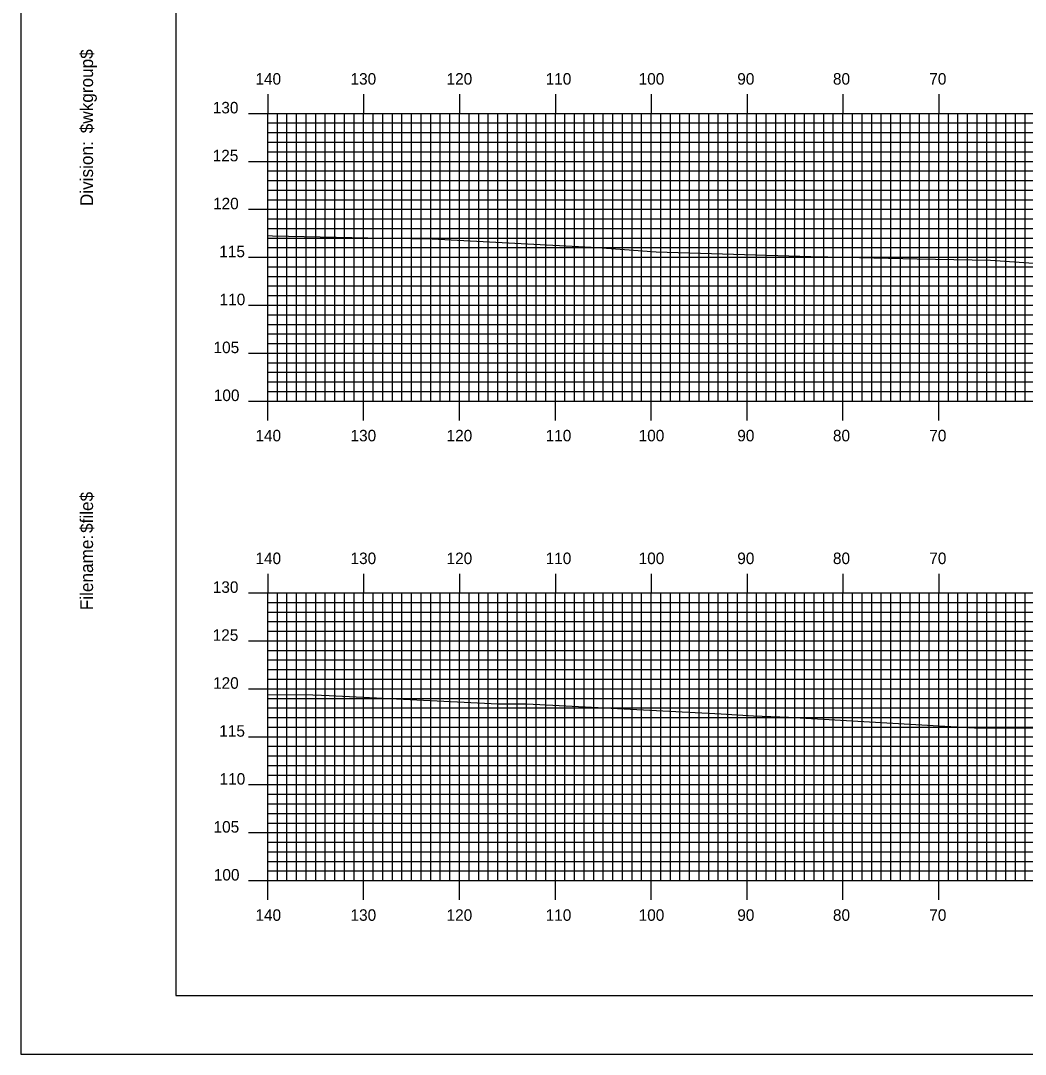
# Model space of a CAD drawing. Extents: x 1781073 to 1781416, y 442591 to 442811.
# Drawn here: x 1781073.1 to 1781177.9, y 442590.5 to 442698.3 of the extents above; entities that cross this region are included whole.
import ezdxf

# ---------------------------------------------------------------- set-up
doc = ezdxf.new("R2010")
doc.units = 0
for name, color, linetype in [('BORDER', 7, 'Continuous'), ('H_V ANNOTATION', 7, 'Continuous'), ('MAJOR', 7, 'Continuous'), ('MINOR', 7, 'Continuous'), ('PLOT BOUNDARY', 7, 'Continuous'), ('S_Roadway_Centerline', 7, 'Continuous')]:
    doc.layers.add(name, color=color, linetype=linetype)

msp = doc.modelspace()

# ---------------------------------------------------------------- linework, layer by layer
at = {"layer": 'BORDER'}
msp.add_lwpolyline([(1781089.29, 442596.67), (1781409.29, 442596.67), (1781409.29, 442806.67), (1781089.29, 442806.67)], close=True, dxfattribs=at)
at = {"layer": 'MAJOR'}
for p, q in [((1781098.89, 442690.67), (1781098.89, 442688.67)), ((1781108.89, 442690.67), (1781108.89, 442688.67)), ((1781118.89, 442690.67), (1781118.89, 442688.67)), ((1781128.89, 442690.67), (1781128.89, 442688.67)), ((1781138.89, 442690.67), (1781138.89, 442688.67)), ((1781148.89, 442690.67), (1781148.89, 442688.67)), ((1781158.89, 442690.67), (1781158.89, 442688.67)), ((1781168.89, 442690.67), (1781168.89, 442688.67)), ((1781096.89, 442688.67), (1781098.89, 442688.67)), ((1781098.89, 442688.67), (1781378.89, 442688.67)), ((1781098.89, 442658.67), (1781098.89, 442688.67)), ((1781098.89, 442658.67), (1781098.89, 442688.67)), ((1781098.89, 442688.67), (1781378.89, 442688.67)), ((1781108.89, 442658.67), (1781108.89, 442688.67)), ((1781118.89, 442658.67), (1781118.89, 442688.67)), ((1781128.89, 442658.67), (1781128.89, 442688.67)), ((1781138.89, 442658.67), (1781138.89, 442688.67)), ((1781148.89, 442658.67), (1781148.89, 442688.67)), ((1781158.89, 442658.67), (1781158.89, 442688.67)), ((1781168.89, 442658.67), (1781168.89, 442688.67)), ((1781096.89, 442683.67), (1781098.89, 442683.67)), ((1781098.89, 442683.67), (1781378.89, 442683.67)), ((1781096.89, 442678.67), (1781098.89, 442678.67)), ((1781098.89, 442678.67), (1781378.89, 442678.67)), ((1781096.89, 442673.67), (1781098.89, 442673.67)), ((1781098.89, 442673.67), (1781378.89, 442673.67)), ((1781096.89, 442668.67), (1781098.89, 442668.67)), ((1781098.89, 442668.67), (1781378.89, 442668.67)), ((1781096.89, 442663.67), (1781098.89, 442663.67)), ((1781098.89, 442663.67), (1781378.89, 442663.67)), ((1781096.89, 442658.67), (1781098.89, 442658.67)), ((1781098.89, 442658.67), (1781378.89, 442658.67)), ((1781098.89, 442658.67), (1781378.89, 442658.67)), ((1781098.89, 442656.66), (1781098.89, 442658.67)), ((1781108.89, 442656.66), (1781108.89, 442658.67)), ((1781118.89, 442656.66), (1781118.89, 442658.67)), ((1781128.89, 442656.66), (1781128.89, 442658.67)), ((1781138.89, 442656.66), (1781138.89, 442658.67)), ((1781148.89, 442656.66), (1781148.89, 442658.67)), ((1781158.89, 442656.66), (1781158.89, 442658.67)), ((1781168.89, 442656.66), (1781168.89, 442658.67)), ((1781098.89, 442640.67), (1781098.89, 442638.67)), ((1781108.89, 442640.67), (1781108.89, 442638.67)), ((1781118.89, 442640.67), (1781118.89, 442638.67)), ((1781128.89, 442640.67), (1781128.89, 442638.67)), ((1781138.89, 442640.67), (1781138.89, 442638.67)), ((1781148.89, 442640.67), (1781148.89, 442638.67)), ((1781158.89, 442640.67), (1781158.89, 442638.67)), ((1781168.89, 442640.67), (1781168.89, 442638.67)), ((1781096.89, 442638.67), (1781098.89, 442638.67)), ((1781098.89, 442638.67), (1781378.89, 442638.67)), ((1781098.89, 442608.67), (1781098.89, 442638.67)), ((1781098.89, 442608.67), (1781098.89, 442638.67)), ((1781098.89, 442638.67), (1781378.89, 442638.67)), ((1781108.89, 442608.67), (1781108.89, 442638.67)), ((1781118.89, 442608.67), (1781118.89, 442638.67)), ((1781128.89, 442608.67), (1781128.89, 442638.67)), ((1781138.89, 442608.67), (1781138.89, 442638.67)), ((1781148.89, 442608.67), (1781148.89, 442638.67)), ((1781158.89, 442608.67), (1781158.89, 442638.67)), ((1781168.89, 442608.67), (1781168.89, 442638.67)), ((1781096.89, 442633.67), (1781098.89, 442633.67)), ((1781098.89, 442633.67), (1781378.89, 442633.67)), ((1781096.89, 442628.67), (1781098.89, 442628.67)), ((1781098.89, 442628.67), (1781378.89, 442628.67)), ((1781096.89, 442623.67), (1781098.89, 442623.67)), ((1781098.89, 442623.67), (1781378.89, 442623.67)), ((1781096.89, 442618.67), (1781098.89, 442618.67)), ((1781098.89, 442618.67), (1781378.89, 442618.67)), ((1781096.89, 442613.67), (1781098.89, 442613.67)), ((1781098.89, 442613.67), (1781378.89, 442613.67)), ((1781096.89, 442608.67), (1781098.89, 442608.67)), ((1781098.89, 442608.67), (1781378.89, 442608.67)), ((1781098.89, 442608.67), (1781378.89, 442608.67)), ((1781098.89, 442606.66), (1781098.89, 442608.67)), ((1781108.89, 442606.66), (1781108.89, 442608.67)), ((1781118.89, 442606.66), (1781118.89, 442608.67)), ((1781128.89, 442606.66), (1781128.89, 442608.67)), ((1781138.89, 442606.66), (1781138.89, 442608.67)), ((1781148.89, 442606.66), (1781148.89, 442608.67)), ((1781158.89, 442606.66), (1781158.89, 442608.67)), ((1781168.89, 442606.66), (1781168.89, 442608.67))]:
    msp.add_line(p, q, dxfattribs=at)
at = {"layer": 'MINOR'}
for p, q in [((1781099.89, 442658.67), (1781099.89, 442688.67)), ((1781100.89, 442658.67), (1781100.89, 442688.67)), ((1781101.89, 442658.67), (1781101.89, 442688.67)), ((1781102.89, 442658.67), (1781102.89, 442688.67)), ((1781103.89, 442658.67), (1781103.89, 442688.67)), ((1781104.89, 442658.67), (1781104.89, 442688.67)), ((1781105.89, 442658.67), (1781105.89, 442688.67)), ((1781106.89, 442658.67), (1781106.89, 442688.67)), ((1781107.89, 442658.67), (1781107.89, 442688.67)), ((1781109.89, 442658.67), (1781109.89, 442688.67)), ((1781110.89, 442658.67), (1781110.89, 442688.67)), ((1781111.89, 442658.67), (1781111.89, 442688.67)), ((1781112.89, 442658.67), (1781112.89, 442688.67)), ((1781113.89, 442658.67), (1781113.89, 442688.67)), ((1781114.89, 442658.67), (1781114.89, 442688.67)), ((1781115.89, 442658.67), (1781115.89, 442688.67)), ((1781116.89, 442658.67), (1781116.89, 442688.67)), ((1781117.89, 442658.67), (1781117.89, 442688.67)), ((1781119.89, 442658.67), (1781119.89, 442688.67)), ((1781120.89, 442658.67), (1781120.89, 442688.67)), ((1781121.89, 442658.67), (1781121.89, 442688.67)), ((1781122.89, 442658.67), (1781122.89, 442688.67)), ((1781123.89, 442658.67), (1781123.89, 442688.67)), ((1781124.89, 442658.67), (1781124.89, 442688.67)), ((1781125.89, 442658.67), (1781125.89, 442688.67)), ((1781126.89, 442658.67), (1781126.89, 442688.67)), ((1781127.89, 442658.67), (1781127.89, 442688.67)), ((1781129.89, 442658.67), (1781129.89, 442688.67)), ((1781130.89, 442658.67), (1781130.89, 442688.67)), ((1781131.89, 442658.67), (1781131.89, 442688.67)), ((1781132.89, 442658.67), (1781132.89, 442688.67)), ((1781133.89, 442658.67), (1781133.89, 442688.67)), ((1781134.89, 442658.67), (1781134.89, 442688.67)), ((1781135.89, 442658.67), (1781135.89, 442688.67)), ((1781136.89, 442658.67), (1781136.89, 442688.67)), ((1781137.89, 442658.67), (1781137.89, 442688.67)), ((1781139.89, 442658.67), (1781139.89, 442688.67)), ((1781140.89, 442658.67), (1781140.89, 442688.67)), ((1781141.89, 442658.67), (1781141.89, 442688.67)), ((1781142.89, 442658.67), (1781142.89, 442688.67)), ((1781143.89, 442658.67), (1781143.89, 442688.67)), ((1781144.89, 442658.67), (1781144.89, 442688.67)), ((1781145.89, 442658.67), (1781145.89, 442688.67)), ((1781146.89, 442658.67), (1781146.89, 442688.67)), ((1781147.89, 442658.67), (1781147.89, 442688.67)), ((1781149.89, 442658.67), (1781149.89, 442688.67)), ((1781150.89, 442658.67), (1781150.89, 442688.67)), ((1781151.89, 442658.67), (1781151.89, 442688.67)), ((1781152.89, 442658.67), (1781152.89, 442688.67)), ((1781153.89, 442658.67), (1781153.89, 442688.67)), ((1781154.89, 442658.67), (1781154.89, 442688.67)), ((1781155.89, 442658.67), (1781155.89, 442688.67)), ((1781156.89, 442658.67), (1781156.89, 442688.67)), ((1781157.89, 442658.67), (1781157.89, 442688.67)), ((1781159.89, 442658.67), (1781159.89, 442688.67)), ((1781160.89, 442658.67), (1781160.89, 442688.67)), ((1781161.89, 442658.67), (1781161.89, 442688.67)), ((1781162.89, 442658.67), (1781162.89, 442688.67)), ((1781163.89, 442658.67), (1781163.89, 442688.67)), ((1781164.89, 442658.67), (1781164.89, 442688.67)), ((1781165.89, 442658.67), (1781165.89, 442688.67)), ((1781166.89, 442658.67), (1781166.89, 442688.67)), ((1781167.89, 442658.67), (1781167.89, 442688.67)), ((1781169.89, 442658.67), (1781169.89, 442688.67)), ((1781170.89, 442658.67), (1781170.89, 442688.67)), ((1781171.89, 442658.67), (1781171.89, 442688.67)), ((1781172.89, 442658.67), (1781172.89, 442688.67)), ((1781173.89, 442658.67), (1781173.89, 442688.67)), ((1781174.89, 442658.67), (1781174.89, 442688.67)), ((1781175.89, 442658.67), (1781175.89, 442688.67)), ((1781176.89, 442658.67), (1781176.89, 442688.67)), ((1781177.89, 442658.67), (1781177.89, 442688.67)), ((1781098.89, 442687.67), (1781378.89, 442687.67)), ((1781098.89, 442687.67), (1781100.9, 442687.67)), ((1781098.89, 442686.67), (1781378.89, 442686.67)), ((1781098.89, 442686.67), (1781100.9, 442686.67)), ((1781098.89, 442685.67), (1781378.89, 442685.67)), ((1781098.89, 442685.67), (1781100.9, 442685.67)), ((1781098.89, 442684.67), (1781378.89, 442684.67)), ((1781098.89, 442684.67), (1781100.9, 442684.67)), ((1781098.89, 442682.67), (1781378.89, 442682.67)), ((1781098.89, 442682.67), (1781100.9, 442682.67)), ((1781098.89, 442681.67), (1781378.89, 442681.67)), ((1781098.89, 442681.67), (1781100.9, 442681.67)), ((1781098.89, 442680.67), (1781378.89, 442680.67)), ((1781098.89, 442680.67), (1781100.9, 442680.67)), ((1781098.89, 442679.67), (1781378.89, 442679.67)), ((1781098.89, 442679.67), (1781100.9, 442679.67)), ((1781098.89, 442677.67), (1781378.89, 442677.67)), ((1781098.89, 442677.67), (1781100.9, 442677.67)), ((1781098.89, 442676.67), (1781378.89, 442676.67)), ((1781098.89, 442676.67), (1781100.9, 442676.67)), ((1781098.89, 442675.67), (1781378.89, 442675.67)), ((1781098.89, 442675.67), (1781100.9, 442675.67)), ((1781098.89, 442674.67), (1781378.89, 442674.67)), ((1781098.89, 442674.67), (1781100.9, 442674.67)), ((1781098.89, 442672.67), (1781378.89, 442672.67)), ((1781098.89, 442672.67), (1781100.9, 442672.67)), ((1781098.89, 442671.67), (1781378.89, 442671.67)), ((1781098.89, 442671.67), (1781100.9, 442671.67)), ((1781098.89, 442670.67), (1781378.89, 442670.67)), ((1781098.89, 442670.67), (1781100.9, 442670.67)), ((1781098.89, 442669.67), (1781378.89, 442669.67)), ((1781098.89, 442669.67), (1781100.9, 442669.67)), ((1781098.89, 442667.67), (1781378.89, 442667.67)), ((1781098.89, 442667.67), (1781100.9, 442667.67)), ((1781098.89, 442666.67), (1781378.89, 442666.67)), ((1781098.89, 442666.67), (1781100.9, 442666.67)), ((1781098.89, 442665.67), (1781378.89, 442665.67)), ((1781098.89, 442665.67), (1781100.9, 442665.67)), ((1781098.89, 442664.67), (1781378.89, 442664.67)), ((1781098.89, 442664.67), (1781100.9, 442664.67)), ((1781098.89, 442662.67), (1781378.89, 442662.67)), ((1781098.89, 442662.67), (1781100.9, 442662.67)), ((1781098.89, 442661.67), (1781378.89, 442661.67)), ((1781098.89, 442661.67), (1781100.9, 442661.67)), ((1781098.89, 442660.67), (1781378.89, 442660.67)), ((1781098.89, 442660.67), (1781100.9, 442660.67)), ((1781098.89, 442659.67), (1781378.89, 442659.67)), ((1781098.89, 442659.67), (1781100.9, 442659.67)), ((1781099.89, 442608.67), (1781099.89, 442638.67)), ((1781100.89, 442608.67), (1781100.89, 442638.67)), ((1781101.89, 442608.67), (1781101.89, 442638.67)), ((1781102.89, 442608.67), (1781102.89, 442638.67)), ((1781103.89, 442608.67), (1781103.89, 442638.67)), ((1781104.89, 442608.67), (1781104.89, 442638.67)), ((1781105.89, 442608.67), (1781105.89, 442638.67)), ((1781106.89, 442608.67), (1781106.89, 442638.67)), ((1781107.89, 442608.67), (1781107.89, 442638.67)), ((1781109.89, 442608.67), (1781109.89, 442638.67)), ((1781110.89, 442608.67), (1781110.89, 442638.67)), ((1781111.89, 442608.67), (1781111.89, 442638.67)), ((1781112.89, 442608.67), (1781112.89, 442638.67)), ((1781113.89, 442608.67), (1781113.89, 442638.67)), ((1781114.89, 442608.67), (1781114.89, 442638.67)), ((1781115.89, 442608.67), (1781115.89, 442638.67)), ((1781116.89, 442608.67), (1781116.89, 442638.67)), ((1781117.89, 442608.67), (1781117.89, 442638.67)), ((1781119.89, 442608.67), (1781119.89, 442638.67)), ((1781120.89, 442608.67), (1781120.89, 442638.67)), ((1781121.89, 442608.67), (1781121.89, 442638.67)), ((1781122.89, 442608.67), (1781122.89, 442638.67)), ((1781123.89, 442608.67), (1781123.89, 442638.67)), ((1781124.89, 442608.67), (1781124.89, 442638.67)), ((1781125.89, 442608.67), (1781125.89, 442638.67)), ((1781126.89, 442608.67), (1781126.89, 442638.67)), ((1781127.89, 442608.67), (1781127.89, 442638.67)), ((1781129.89, 442608.67), (1781129.89, 442638.67)), ((1781130.89, 442608.67), (1781130.89, 442638.67)), ((1781131.89, 442608.67), (1781131.89, 442638.67)), ((1781132.89, 442608.67), (1781132.89, 442638.67)), ((1781133.89, 442608.67), (1781133.89, 442638.67)), ((1781134.89, 442608.67), (1781134.89, 442638.67)), ((1781135.89, 442608.67), (1781135.89, 442638.67)), ((1781136.89, 442608.67), (1781136.89, 442638.67)), ((1781137.89, 442608.67), (1781137.89, 442638.67)), ((1781139.89, 442608.67), (1781139.89, 442638.67)), ((1781140.89, 442608.67), (1781140.89, 442638.67)), ((1781141.89, 442608.67), (1781141.89, 442638.67)), ((1781142.89, 442608.67), (1781142.89, 442638.67)), ((1781143.89, 442608.67), (1781143.89, 442638.67)), ((1781144.89, 442608.67), (1781144.89, 442638.67)), ((1781145.89, 442608.67), (1781145.89, 442638.67)), ((1781146.89, 442608.67), (1781146.89, 442638.67)), ((1781147.89, 442608.67), (1781147.89, 442638.67)), ((1781149.89, 442608.67), (1781149.89, 442638.67)), ((1781150.89, 442608.67), (1781150.89, 442638.67)), ((1781151.89, 442608.67), (1781151.89, 442638.67)), ((1781152.89, 442608.67), (1781152.89, 442638.67)), ((1781153.89, 442608.67), (1781153.89, 442638.67)), ((1781154.89, 442608.67), (1781154.89, 442638.67)), ((1781155.89, 442608.67), (1781155.89, 442638.67)), ((1781156.89, 442608.67), (1781156.89, 442638.67)), ((1781157.89, 442608.67), (1781157.89, 442638.67)), ((1781159.89, 442608.67), (1781159.89, 442638.67)), ((1781160.89, 442608.67), (1781160.89, 442638.67)), ((1781161.89, 442608.67), (1781161.89, 442638.67)), ((1781162.89, 442608.67), (1781162.89, 442638.67)), ((1781163.89, 442608.67), (1781163.89, 442638.67)), ((1781164.89, 442608.67), (1781164.89, 442638.67)), ((1781165.89, 442608.67), (1781165.89, 442638.67)), ((1781166.89, 442608.67), (1781166.89, 442638.67)), ((1781167.89, 442608.67), (1781167.89, 442638.67)), ((1781169.89, 442608.67), (1781169.89, 442638.67)), ((1781170.89, 442608.67), (1781170.89, 442638.67)), ((1781171.89, 442608.67), (1781171.89, 442638.67)), ((1781172.89, 442608.67), (1781172.89, 442638.67)), ((1781173.89, 442608.67), (1781173.89, 442638.67)), ((1781174.89, 442608.67), (1781174.89, 442638.67)), ((1781175.89, 442608.67), (1781175.89, 442638.67)), ((1781176.89, 442608.67), (1781176.89, 442638.67)), ((1781177.89, 442608.67), (1781177.89, 442638.67)), ((1781098.89, 442637.67), (1781378.89, 442637.67)), ((1781098.89, 442637.67), (1781100.9, 442637.67)), ((1781098.89, 442636.67), (1781378.89, 442636.67)), ((1781098.89, 442636.67), (1781100.9, 442636.67)), ((1781098.89, 442635.67), (1781378.89, 442635.67)), ((1781098.89, 442635.67), (1781100.9, 442635.67)), ((1781098.89, 442634.67), (1781378.89, 442634.67)), ((1781098.89, 442634.67), (1781100.9, 442634.67)), ((1781098.89, 442632.67), (1781378.89, 442632.67)), ((1781098.89, 442632.67), (1781100.9, 442632.67)), ((1781098.89, 442631.67), (1781378.89, 442631.67)), ((1781098.89, 442631.67), (1781100.9, 442631.67)), ((1781098.89, 442630.67), (1781378.89, 442630.67)), ((1781098.89, 442630.67), (1781100.9, 442630.67)), ((1781098.89, 442629.67), (1781378.89, 442629.67)), ((1781098.89, 442629.67), (1781100.9, 442629.67)), ((1781098.89, 442627.67), (1781378.89, 442627.67)), ((1781098.89, 442627.67), (1781100.9, 442627.67)), ((1781098.89, 442626.67), (1781378.89, 442626.67)), ((1781098.89, 442626.67), (1781100.9, 442626.67)), ((1781098.89, 442625.67), (1781378.89, 442625.67)), ((1781098.89, 442625.67), (1781100.9, 442625.67)), ((1781098.89, 442624.67), (1781378.89, 442624.67)), ((1781098.89, 442624.67), (1781100.9, 442624.67)), ((1781098.89, 442622.67), (1781378.89, 442622.67)), ((1781098.89, 442622.67), (1781100.9, 442622.67)), ((1781098.89, 442621.67), (1781378.89, 442621.67)), ((1781098.89, 442621.67), (1781100.9, 442621.67)), ((1781098.89, 442620.67), (1781378.89, 442620.67)), ((1781098.89, 442620.67), (1781100.9, 442620.67)), ((1781098.89, 442619.67), (1781378.89, 442619.67)), ((1781098.89, 442619.67), (1781100.9, 442619.67)), ((1781098.89, 442617.67), (1781378.89, 442617.67)), ((1781098.89, 442617.67), (1781100.9, 442617.67)), ((1781098.89, 442616.67), (1781378.89, 442616.67)), ((1781098.89, 442616.67), (1781100.9, 442616.67)), ((1781098.89, 442615.67), (1781378.89, 442615.67)), ((1781098.89, 442615.67), (1781100.9, 442615.67)), ((1781098.89, 442614.67), (1781378.89, 442614.67)), ((1781098.89, 442614.67), (1781100.9, 442614.67)), ((1781098.89, 442612.67), (1781378.89, 442612.67)), ((1781098.89, 442612.67), (1781100.9, 442612.67)), ((1781098.89, 442611.67), (1781378.89, 442611.67)), ((1781098.89, 442611.67), (1781100.9, 442611.67)), ((1781098.89, 442610.67), (1781378.89, 442610.67)), ((1781098.89, 442610.67), (1781100.9, 442610.67)), ((1781098.89, 442609.67), (1781378.89, 442609.67)), ((1781098.89, 442609.67), (1781100.9, 442609.67))]:
    msp.add_line(p, q, dxfattribs=at)
at = {"layer": 'PLOT BOUNDARY'}
msp.add_lwpolyline([(1781073.11, 442590.55), (1781413.11, 442590.55), (1781413.11, 442810.55), (1781073.11, 442810.55)], close=True, dxfattribs=at)
at = {"layer": 'S_Roadway_Centerline'}
for points in [[(1781098.89, 442675.92), (1781099.37, 442675.91), (1781109.34, 442675.68), (1781116.04, 442675.6), (1781133.29, 442674.67), (1781139.41, 442674.24), (1781155.55, 442673.73), (1781159.14, 442673.66), (1781166.65, 442673.52), (1781174.3, 442673.36), (1781181.76, 442672.85)], [(1781098.89, 442628.06), (1781103.59, 442628.04), (1781104.49, 442627.99), (1781105.31, 442627.95), (1781122.88, 442627.1), (1781125.92, 442627.09), (1781146.2, 442626.06), (1781149.56, 442625.83), (1781153.21, 442625.72), (1781169.54, 442624.77), (1781172.63, 442624.6), (1781192.65, 442624.57)]]:
    msp.add_lwpolyline(points, dxfattribs=at)

# ---------------------------------------------------------------- texts
at = {"layer": 'BORDER'}
for s, p in [('$wkgroup$', (1781080.66, 442686.6)), ('Division:', (1781080.66, 442679)), ('$file$', (1781080.66, 442644.92)), ('Filename:', (1781080.66, 442636.86))]:
    msp.add_text(s, height=1.339, rotation=90, dxfattribs=at).set_placement(p)
at = {"layer": 'H_V ANNOTATION'}
for s, p in [('140', (1781097.6, 442691.67)), ('130', (1781107.52, 442691.67)), ('120', (1781117.54, 442691.67)), ('110', (1781127.88, 442691.67)), ('100', (1781137.58, 442691.67)), ('90', (1781147.87, 442691.67)), ('80', (1781157.85, 442691.67)), ('70', (1781167.9, 442691.67)), ('130', (1781093.15, 442688.67)), ('125', (1781093.14, 442683.67)), ('120', (1781093.18, 442678.67)), ('115', (1781093.83, 442673.67)), ('110', (1781093.86, 442668.67)), ('105', (1781093.23, 442663.67)), ('100', (1781093.26, 442658.67)), ('140', (1781097.6, 442654.47)), ('130', (1781107.52, 442654.47)), ('120', (1781117.54, 442654.47)), ('110', (1781127.88, 442654.47)), ('100', (1781137.58, 442654.47)), ('90', (1781147.87, 442654.47)), ('80', (1781157.85, 442654.47)), ('70', (1781167.9, 442654.47)), ('140', (1781097.6, 442641.67)), ('130', (1781107.52, 442641.67)), ('120', (1781117.54, 442641.67)), ('110', (1781127.88, 442641.67)), ('100', (1781137.58, 442641.67)), ('90', (1781147.87, 442641.67)), ('80', (1781157.85, 442641.67)), ('70', (1781167.9, 442641.67)), ('130', (1781093.15, 442638.67)), ('125', (1781093.14, 442633.67)), ('120', (1781093.18, 442628.67)), ('115', (1781093.83, 442623.67)), ('110', (1781093.86, 442618.67)), ('105', (1781093.23, 442613.67)), ('100', (1781093.26, 442608.67)), ('140', (1781097.6, 442604.47)), ('130', (1781107.52, 442604.47)), ('120', (1781117.54, 442604.47)), ('110', (1781127.88, 442604.47)), ('100', (1781137.58, 442604.47)), ('90', (1781147.87, 442604.47)), ('80', (1781157.85, 442604.47)), ('70', (1781167.9, 442604.47))]:
    msp.add_text(s, height=1.2, dxfattribs=at).set_placement(p)
at = {"layer": 'MAJOR'}
for p in [(1781098.89, 442658.67), (1781098.89, 442608.67)]:
    msp.add_text('-', height=0.012, dxfattribs=at).set_placement(p)

doc.saveas('drawing.dxf')
